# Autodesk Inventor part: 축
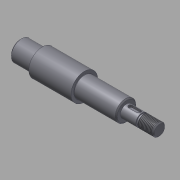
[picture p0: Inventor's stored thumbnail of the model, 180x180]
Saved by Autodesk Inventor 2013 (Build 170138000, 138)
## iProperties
Created: 2015-12
Part Number: 축
Material: 강철, 연강
Document SubType Name: Modeling
Designer: mdu
Density: 7.86 g/cm^3
Mass: 350.729 g
Surface Area: 95.1089 cm^2
Volume: 44.6221 cm^3
CustomPartVersion: 1
Author: mdu
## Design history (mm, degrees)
sketch "스케치5"
  geometry: L1 (0, 0)-(135, 0); L2 (0, 0)-(135, 0); L3 (135, 0)-(135, 6); L4 (103, 6)-(103, 10); L5 (103, 10)-(62, 10); L6 (62, 10)-(62, 13); L7 (62, 13)-(21, 13); L8 (21, 13)-(21, 10); L9 (21, 10)-(0, 10); L10 (0, 10)-(0, 0); L11 (118, 6)-(118, 5); L12 (118, 5)-(120, 5); L13 (120, 5)-(120, 6); L14 (135, 6)-(120, 6); L15 (118, 6)-(103, 6)
  constraints: 31 end point, 12 perpendicular, 9 parallel, 1 collinear, 1 horizontal
  dimensions: "d43" = 20 diameter of L9 L1; "d44" = 26 diameter of L7 L1; "d45" = 20 diameter of L5 L2; "d47" = 41 distance of L6.end L7.end; "d48" = 32 distance between parallel lines of L3 L4; "d50" = 21 distance of L8.end L9.end; "d52" = 12 diameter of L14 L1; "d53" = 15 distance between parallel lines of L3 L13; "d54" = 2 distance of L11.end L12.end; "d55" = 1 distance between parallel lines of L14 L12; "d64" = 135 distance of L1.start L1.end
revolve "회전4" sketch "스케치5" stored, may be unused: angle "d51" = 90 deg
feature "스레드6" dims "d56" = 10, "d57" = 0
chamfer "모따기6" distance "d32" = 1; stored, may be unused: second distance "d33" = 0.4, angle "d34" = 45 deg
chamfer "모따기5" distance "d27" = 1; stored, may be unused: second distance "d28" = 0.125, angle "d29" = 45 deg
fillet "모깎기1" dims "d17" = 0.3
fillet "모깎기2" dims "d18" = 0.3
chamfer "모따기3" distance "d19" = 1; stored, may be unused: second distance "d20" = 1, angle "d21" = 45 deg
node "작업 평면1"
sketch "스케치6"
  geometry: L1 (-3.5, 2)-(4.5, 2); L2 (4.5, -2)-(-3.5, -2); L3 (-7.5, 9)-(-7.5, -9) reference; A1 r 2 centre (4.5, 0) between (4.5, -2) and (4.5, 2); A2 r 2 centre (-3.5, 0) between (-3.5, 2) and (-3.5, -2); 1 further point
  constraints: 4 end point, 4 point on circle, 4 tangent, 2 centre point, 1 horizontal, 1 horizontal alignment, 1 parallel
  dimensions: "d59" = 2 distance edge to line of A2 L3; "d60" = 12 dimension on A1 A2; "d61" = 4 distance between parallel lines of L2 L1
extrude "돌출1" cut sketch "스케치6" distance "d62" = 2.3; taper "d63" = 0 deg
node "솔리드1"
node "솔리드2"
other parameters: "d46" = 12
